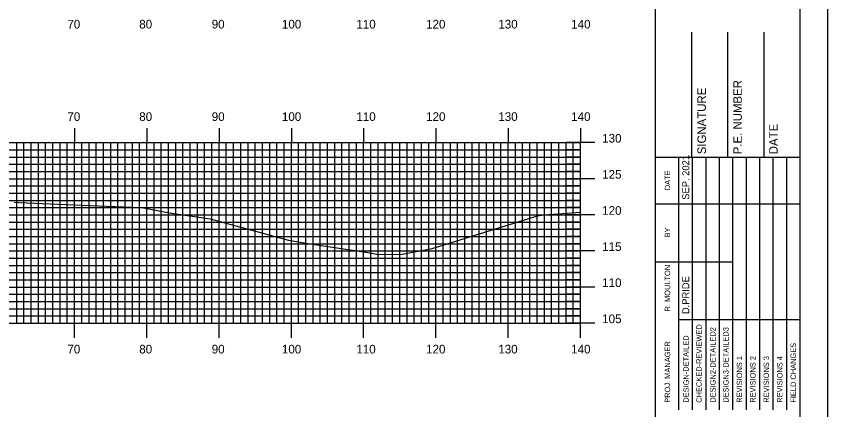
# Model space of a CAD drawing. Extents: x 854287 to 854631, y 366605 to 366825.
# Drawn here: x 854515 to 854627.3, y 366701.1 to 366755.6 of the extents above; entities that cross this region are included whole.
import ezdxf

# ---------------------------------------------------------------- set-up
doc = ezdxf.new("R2010")
doc.units = 0
for name, color, linetype in [('BORDER', 7, 'Continuous'), ('H_V ANNOTATION', 7, 'Continuous'), ('MAJOR', 7, 'Continuous'), ('MINOR', 7, 'Continuous'), ('PLOT BOUNDARY', 7, 'Continuous'), ('S_Roadway_Centerline', 7, 'Continuous')]:
    doc.layers.add(name, color=color, linetype=linetype)

msp = doc.modelspace()

# ---------------------------------------------------------------- linework, layer by layer
at = {"layer": 'BORDER'}
for p, q in [((854603.44, 366611.06), (854603.44, 366821.06)), ((854608.44, 366736.06), (854608.44, 366753.36)), ((854613.44, 366736.06), (854613.44, 366753.36)), ((854618.44, 366736.06), (854618.44, 366753.36)), ((854603.44, 366736.06), (854623.44, 366736.06))]:
    msp.add_line(p, q, dxfattribs=at)
msp.add_lwpolyline([(854303.44, 366611.06), (854623.44, 366611.06), (854623.44, 366821.06), (854303.44, 366821.06)], close=True, dxfattribs=at)
for points in [[(854606.67, 366729.56), (854606.67, 366736.06)], [(854608.54, 366701.07), (854608.54, 366736.06)], [(854610.4, 366736.06), (854610.4, 366701.07)], [(854612.26, 366701.07), (854612.26, 366736.06)], [(854614.13, 366701.07), (854614.13, 366736.06)], [(854615.99, 366701.07), (854615.99, 366736.06)], [(854617.85, 366701.07), (854617.85, 366736.06)], [(854619.72, 366701.07), (854619.72, 366736.06)], [(854621.58, 366701.07), (854621.58, 366736.06)], [(854606.67, 366701.07), (854606.67, 366734.65)], [(854603.44, 366729.56), (854623.44, 366729.56)], [(854603.44, 366721.56), (854606.67, 366721.56)], [(854606.67, 366721.56), (854614.13, 366721.56)], [(854606.67, 366713.56), (854623.44, 366713.56)]]:
    msp.add_lwpolyline(points, dxfattribs=at)
at = {"layer": 'MAJOR'}
for p, q in [((854523.04, 366740.06), (854523.04, 366738.06)), ((854533.04, 366740.06), (854533.04, 366738.06)), ((854543.04, 366740.06), (854543.04, 366738.06)), ((854553.04, 366740.06), (854553.04, 366738.06)), ((854563.04, 366740.06), (854563.04, 366738.06)), ((854573.04, 366740.06), (854573.04, 366738.06)), ((854583.04, 366740.06), (854583.04, 366738.06)), ((854593.04, 366740.06), (854593.04, 366738.06)), ((854313.04, 366738.06), (854593.04, 366738.06)), ((854313.04, 366738.06), (854593.04, 366738.06)), ((854523.04, 366713.06), (854523.04, 366738.06)), ((854533.04, 366713.06), (854533.04, 366738.06)), ((854543.04, 366713.06), (854543.04, 366738.06)), ((854553.04, 366713.06), (854553.04, 366738.06)), ((854563.04, 366713.06), (854563.04, 366738.06)), ((854573.04, 366713.06), (854573.04, 366738.06)), ((854583.04, 366713.06), (854583.04, 366738.06)), ((854595.05, 366738.06), (854591.04, 366738.06)), ((854593.04, 366713.06), (854593.04, 366738.06)), ((854593.04, 366713.06), (854593.04, 366738.06)), ((854313.04, 366733.06), (854593.04, 366733.06)), ((854595.05, 366733.06), (854591.04, 366733.06)), ((854313.04, 366728.06), (854593.04, 366728.06)), ((854595.05, 366728.06), (854591.04, 366728.06)), ((854313.04, 366723.06), (854593.04, 366723.06)), ((854595.05, 366723.06), (854591.04, 366723.06)), ((854313.04, 366718.06), (854593.04, 366718.06)), ((854595.05, 366718.06), (854591.04, 366718.06)), ((854313.04, 366713.06), (854593.04, 366713.06)), ((854313.04, 366713.06), (854593.04, 366713.06)), ((854523.04, 366711.05), (854523.04, 366713.06)), ((854533.04, 366711.05), (854533.04, 366713.06)), ((854543.04, 366711.05), (854543.04, 366713.06)), ((854553.04, 366711.05), (854553.04, 366713.06)), ((854563.04, 366711.05), (854563.04, 366713.06)), ((854573.04, 366711.05), (854573.04, 366713.06)), ((854583.04, 366711.05), (854583.04, 366713.06)), ((854595.05, 366713.06), (854591.04, 366713.06)), ((854593.04, 366711.05), (854593.04, 366713.06))]:
    msp.add_line(p, q, dxfattribs=at)
at = {"layer": 'MINOR'}
for p, q in [((854515.04, 366713.06), (854515.04, 366738.06)), ((854516.04, 366713.06), (854516.04, 366738.06)), ((854517.04, 366713.06), (854517.04, 366738.06)), ((854518.04, 366713.06), (854518.04, 366738.06)), ((854519.04, 366713.06), (854519.04, 366738.06)), ((854520.04, 366713.06), (854520.04, 366738.06)), ((854521.04, 366713.06), (854521.04, 366738.06)), ((854522.04, 366713.06), (854522.04, 366738.06)), ((854524.04, 366713.06), (854524.04, 366738.06)), ((854525.04, 366713.06), (854525.04, 366738.06)), ((854526.04, 366713.06), (854526.04, 366738.06)), ((854527.04, 366713.06), (854527.04, 366738.06)), ((854528.04, 366713.06), (854528.04, 366738.06)), ((854529.04, 366713.06), (854529.04, 366738.06)), ((854530.04, 366713.06), (854530.04, 366738.06)), ((854531.04, 366713.06), (854531.04, 366738.06)), ((854532.04, 366713.06), (854532.04, 366738.06)), ((854534.04, 366713.06), (854534.04, 366738.06)), ((854535.04, 366713.06), (854535.04, 366738.06)), ((854536.04, 366713.06), (854536.04, 366738.06)), ((854537.04, 366713.06), (854537.04, 366738.06)), ((854538.04, 366713.06), (854538.04, 366738.06)), ((854539.04, 366713.06), (854539.04, 366738.06)), ((854540.04, 366713.06), (854540.04, 366738.06)), ((854541.04, 366713.06), (854541.04, 366738.06)), ((854542.04, 366713.06), (854542.04, 366738.06)), ((854544.04, 366713.06), (854544.04, 366738.06)), ((854545.04, 366713.06), (854545.04, 366738.06)), ((854546.04, 366713.06), (854546.04, 366738.06)), ((854547.04, 366713.06), (854547.04, 366738.06)), ((854548.04, 366713.06), (854548.04, 366738.06)), ((854549.04, 366713.06), (854549.04, 366738.06)), ((854550.04, 366713.06), (854550.04, 366738.06)), ((854551.04, 366713.06), (854551.04, 366738.06)), ((854552.04, 366713.06), (854552.04, 366738.06)), ((854554.04, 366713.06), (854554.04, 366738.06)), ((854555.04, 366713.06), (854555.04, 366738.06)), ((854556.04, 366713.06), (854556.04, 366738.06)), ((854557.04, 366713.06), (854557.04, 366738.06)), ((854558.04, 366713.06), (854558.04, 366738.06)), ((854559.04, 366713.06), (854559.04, 366738.06)), ((854560.04, 366713.06), (854560.04, 366738.06)), ((854561.04, 366713.06), (854561.04, 366738.06)), ((854562.04, 366713.06), (854562.04, 366738.06)), ((854564.04, 366713.06), (854564.04, 366738.06)), ((854565.04, 366713.06), (854565.04, 366738.06)), ((854566.04, 366713.06), (854566.04, 366738.06)), ((854567.04, 366713.06), (854567.04, 366738.06)), ((854568.04, 366713.06), (854568.04, 366738.06)), ((854569.04, 366713.06), (854569.04, 366738.06)), ((854570.04, 366713.06), (854570.04, 366738.06)), ((854571.04, 366713.06), (854571.04, 366738.06)), ((854572.04, 366713.06), (854572.04, 366738.06)), ((854574.04, 366713.06), (854574.04, 366738.06)), ((854575.04, 366713.06), (854575.04, 366738.06)), ((854576.04, 366713.06), (854576.04, 366738.06)), ((854577.04, 366713.06), (854577.04, 366738.06)), ((854578.04, 366713.06), (854578.04, 366738.06)), ((854579.04, 366713.06), (854579.04, 366738.06)), ((854580.04, 366713.06), (854580.04, 366738.06)), ((854581.04, 366713.06), (854581.04, 366738.06)), ((854582.04, 366713.06), (854582.04, 366738.06)), ((854584.04, 366713.06), (854584.04, 366738.06)), ((854585.04, 366713.06), (854585.04, 366738.06)), ((854586.04, 366713.06), (854586.04, 366738.06)), ((854587.04, 366713.06), (854587.04, 366738.06)), ((854588.04, 366713.06), (854588.04, 366738.06)), ((854589.04, 366713.06), (854589.04, 366738.06)), ((854590.04, 366713.06), (854590.04, 366738.06)), ((854591.04, 366713.06), (854591.04, 366738.06)), ((854592.04, 366713.06), (854592.04, 366738.06)), ((854313.04, 366737.06), (854593.04, 366737.06)), ((854313.04, 366736.06), (854593.04, 366736.06)), ((854593.04, 366737.06), (854591.04, 366737.06)), ((854593.04, 366736.06), (854591.04, 366736.06)), ((854313.04, 366735.06), (854593.04, 366735.06)), ((854593.04, 366735.06), (854591.04, 366735.06)), ((854313.04, 366734.06), (854593.04, 366734.06)), ((854593.04, 366734.06), (854591.04, 366734.06)), ((854313.04, 366732.06), (854593.04, 366732.06)), ((854593.04, 366732.06), (854591.04, 366732.06)), ((854313.04, 366731.06), (854593.04, 366731.06)), ((854593.04, 366731.06), (854591.04, 366731.06)), ((854313.04, 366730.06), (854593.04, 366730.06)), ((854593.04, 366730.06), (854591.04, 366730.06)), ((854313.04, 366729.06), (854593.04, 366729.06)), ((854593.04, 366729.06), (854591.04, 366729.06)), ((854313.04, 366727.06), (854593.04, 366727.06)), ((854593.04, 366727.06), (854591.04, 366727.06)), ((854313.04, 366726.06), (854593.04, 366726.06)), ((854593.04, 366726.06), (854591.04, 366726.06)), ((854313.04, 366725.06), (854593.04, 366725.06)), ((854593.04, 366725.06), (854591.04, 366725.06)), ((854313.04, 366724.06), (854593.04, 366724.06)), ((854593.04, 366724.06), (854591.04, 366724.06)), ((854313.04, 366722.06), (854593.04, 366722.06)), ((854593.04, 366722.06), (854591.04, 366722.06)), ((854313.04, 366721.06), (854593.04, 366721.06)), ((854593.04, 366721.06), (854591.04, 366721.06)), ((854313.04, 366720.06), (854593.04, 366720.06)), ((854593.04, 366720.06), (854591.04, 366720.06)), ((854313.04, 366719.06), (854593.04, 366719.06)), ((854593.04, 366719.06), (854591.04, 366719.06)), ((854313.04, 366717.06), (854593.04, 366717.06)), ((854593.04, 366717.06), (854591.04, 366717.06)), ((854313.04, 366716.06), (854593.04, 366716.06)), ((854593.04, 366716.06), (854591.04, 366716.06)), ((854313.04, 366715.06), (854593.04, 366715.06)), ((854593.04, 366715.06), (854591.04, 366715.06)), ((854313.04, 366714.06), (854593.04, 366714.06)), ((854593.04, 366714.06), (854591.04, 366714.06))]:
    msp.add_line(p, q, dxfattribs=at)
at = {"layer": 'PLOT BOUNDARY'}
msp.add_lwpolyline([(854287.26, 366604.94), (854627.26, 366604.94), (854627.26, 366824.94), (854287.26, 366824.94)], close=True, dxfattribs=at)
at = {"layer": 'S_Roadway_Centerline'}
msp.add_lwpolyline([(854514.68, 366729.82), (854515.38, 366729.76), (854516.45, 366729.73), (854521.78, 366729.47), (854530.96, 366729.11), (854532.35, 366729.07), (854536.2, 366728.33), (854541.82, 366727.49), (854552.66, 366724.53), (854555.66, 366724.04), (854563.36, 366722.89), (854565.14, 366722.57), (854568.39, 366722.62), (854572.51, 366723.42), (854587.1, 366727.92), (854587.96, 366728.05), (854593.04, 366728.42)], dxfattribs=at)

# ---------------------------------------------------------------- texts
at = {"layer": 'BORDER'}
for s, height, p in [('P.E. NUMBER', 1.1811, (854615.36, 366736.45)), ('SIGNATURE', 1.181, (854610.4, 366736.45)), ('DATE', 1.181, (854620.33, 366736.45)), ('SEP. 2021', 0.969, (854608.09, 366730.15)), ('DATE', 0.743, (854605.45, 366731.47)), ('BY', 0.743, (854605.45, 366724.93)), ('R. MOULTON', 0.745, (854605.45, 366714.67)), ('D.PRIDE', 0.969, (854608.09, 366714.31)), ('CHECKED-REVIEWED', 0.7455, (854609.81, 366702.04)), ('DESIGN2-DETAILED2', 0.7455, (854611.74, 366702.04)), ('DESIGN3-DETAILED3', 0.7455, (854613.53, 366702.04)), ('PROJ. MANAGER', 0.7455, (854605.45, 366702.04)), ('DESIGN-DETAILED', 0.7455, (854608.02, 366702.04)), ('FIELD CHANGES', 0.7455, (854622.85, 366702.04)), ('REVISIONS 1', 0.7455, (854615.4, 366702.04)), ('REVISIONS 2', 0.7455, (854617.26, 366702.04)), ('REVISIONS 3', 0.7455, (854619.12, 366702.04)), ('REVISIONS 4', 0.7455, (854620.99, 366702.04))]:
    msp.add_text(s, height=height, rotation=90, dxfattribs=at).set_placement(p)
at = {"layer": 'H_V ANNOTATION'}
for s, p in [('70', (854522.05, 366753.86)), ('80', (854531.99, 366753.86)), ('90', (854542.02, 366753.86)), ('100', (854551.73, 366753.86)), ('110', (854562.03, 366753.86)), ('120', (854571.68, 366753.86)), ('130', (854581.67, 366753.86)), ('140', (854591.75, 366753.86)), ('70', (854522.05, 366741.06)), ('80', (854531.99, 366741.06)), ('90', (854542.02, 366741.06)), ('100', (854551.73, 366741.06)), ('110', (854562.03, 366741.06)), ('120', (854571.68, 366741.06)), ('130', (854581.67, 366741.06)), ('140', (854591.75, 366741.06)), ('130', (854596.04, 366738.06)), ('125', (854596.04, 366733.06)), ('120', (854596.04, 366728.06)), ('115', (854596.04, 366723.06)), ('110', (854596.04, 366718.06)), ('105', (854596.04, 366713.06)), ('70', (854522.05, 366708.86)), ('80', (854531.99, 366708.86)), ('90', (854542.02, 366708.86)), ('100', (854551.73, 366708.86)), ('110', (854562.03, 366708.86)), ('120', (854571.68, 366708.86)), ('130', (854581.67, 366708.86)), ('140', (854591.75, 366708.86))]:
    msp.add_text(s, height=1.2, dxfattribs=at).set_placement(p)

doc.saveas('drawing.dxf')
